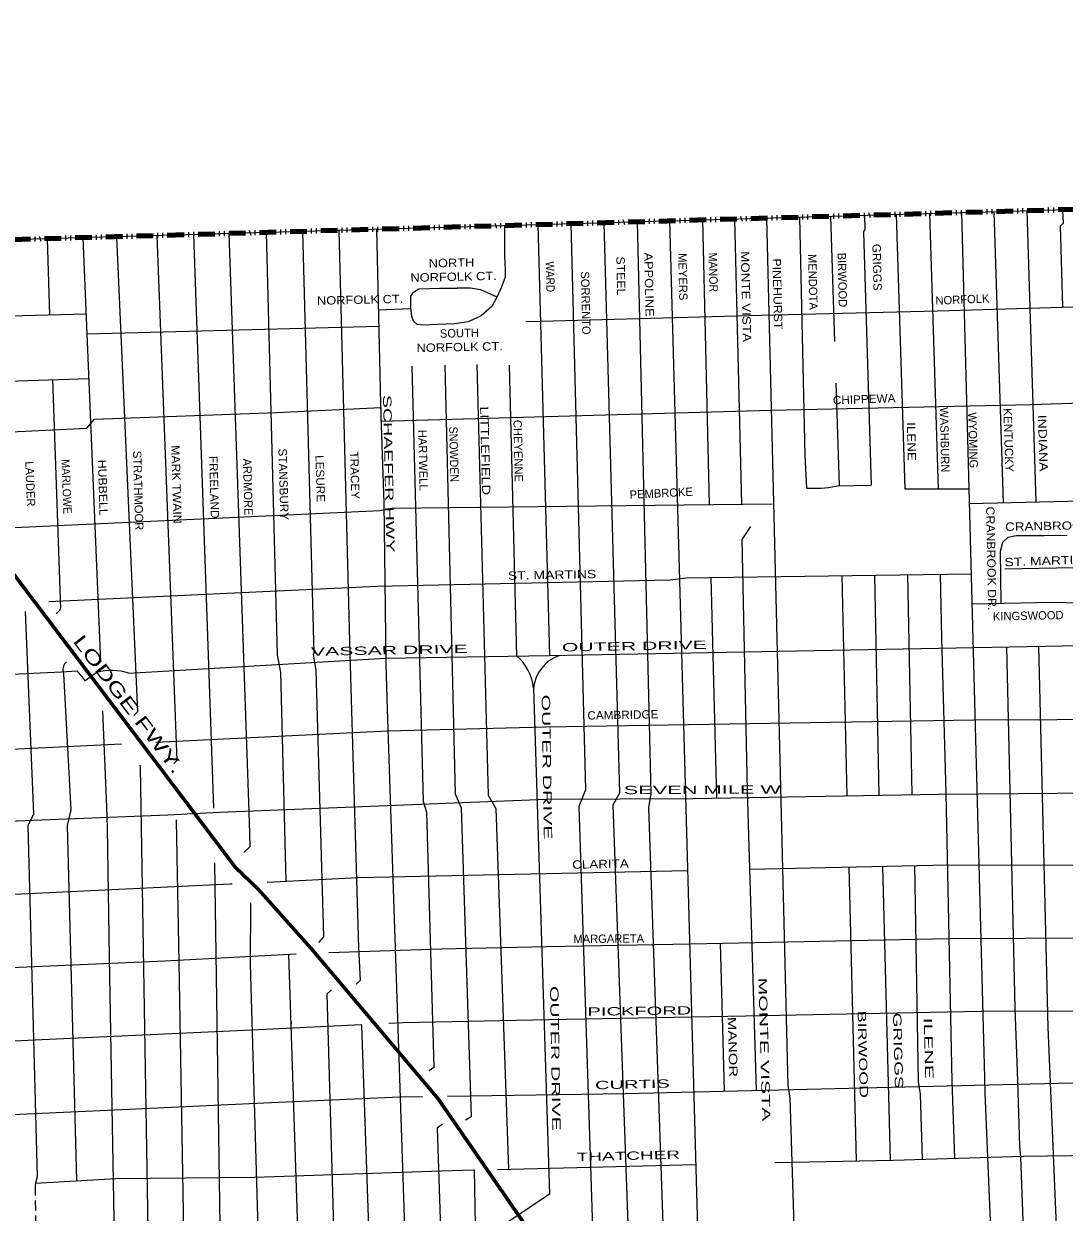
# Model space of a CAD drawing. Extents: x 34705 to 138605, y 34275 to 143551.
# Drawn here: x 60584 to 69930, y 132625 to 143301 of the extents above; entities that cross this region are included whole.
import ezdxf
from ezdxf.enums import TextEntityAlignment as Align

# ---------------------------------------------------------------- set-up
doc = ezdxf.new("R2010")
doc.units = 0
doc.header["$LTSCALE"] = 30
doc.linetypes.add('DASH_DOUBLE_DOT', pattern=[9.2, 5, -1.2, 0.3, -1.2, 0.3, -1.2])
doc.linetypes.add('MEDIUM_DASHED', pattern=[4.5, 3, -1.5])
for name, color, linetype, lineweight in [('1', 7, 'Continuous', 13), ('11', 7, 'Continuous', 13), ('51', 7, 'Continuous', 35), ('59', 7, 'DASH_DOUBLE_DOT', 106)]:
    doc.layers.add(name, color=color, linetype=linetype, lineweight=lineweight)

msp = doc.modelspace()

# ---------------------------------------------------------------- linework, layer by layer
at = {"layer": '1'}
for p, q in [((75780.8, 141796.99), (34922.9, 140631.57)), ((67829.9, 141570.2), (67866.44, 140447.23)), ((68422.1, 141587.09), (68499.45, 139123.37)), ((68719.75, 141595.58), (68796.59, 139123.37)), ((69299.41, 141612.11), (69381.01, 138998.67)), ((69595.74, 141620.57), (69674.85, 139005.55)), ((65202.64, 141495.26), (65306.45, 137625.47)), ((66682.32, 141537.46), (66740.03, 138981.8)), ((66968.64, 141545.63), (67032.3, 138985.16)), ((60795.73, 141369.56), (60815.72, 140686.87)), ((61115.53, 141378.68), (61273.76, 137566.54)), ((62108.83, 141407.01), (62289.02, 136253.43)), ((63769.99, 140730.86), (64061.27, 140743.01)), ((63775.3, 140731.09), (64053.92, 140742.7)), ((59169.39, 140638.51), (61143.85, 140696.51)), ((61151.35, 140515.77), (63773.41, 140585.79)), ((64945.36, 140235.52), (65010.54, 137620.79)), ((59188.11, 140049.59), (61167.99, 140114.8)), ((60843.68, 140104.43), (60913.9, 138048.34)), ((67878.59, 140073.92), (67908.59, 139151.81)), ((68499.45, 139123.37), (68796.18, 139123.37)), ((68796.59, 139123.37), (69073.39, 139123.37)), ((66756.3, 138326.41), (66806.97, 136344.66)), ((67932.67, 138342.52), (67978.14, 136366.05)), ((68225.6, 138346.54), (68265.02, 136371.29)), ((68522.52, 138350.6), (68562.37, 136376.72)), ((61062.26, 137489.13), (61134.92, 137399.56)), ((61240.41, 137472.81), (61134.92, 137399.56)), ((59283.65, 136728.46), (61462.5, 136833.81)), ((67994.83, 135726.36), (68060.94, 133086.13)), ((68297.13, 135732.82), (68367.51, 133092.66)), ((66840.26, 135041.26), (66877.03, 133713.73)), ((62962.12, 134942.93), (63049.9, 132307.68)), ((62984.92, 134336.63), (62985.66, 134313.22)), ((64841.02, 133009.79), (66619.14, 133052.98)), ((69538.12, 133118.98), (69608.88, 131142.6))]:
    msp.add_line(p, q, dxfattribs=at)
at = {"layer": '1', "lineweight": 25}
msp.add_line((69398.11, 138403.72), (70195.7, 138419.82), dxfattribs=at)
at = {"layer": '1'}
for points in [[(68135.27, 141578.91), (68139.56, 141454.62), (68128.57, 141428.99), (68194.72, 139157.43)], [(69007.73, 141603.79), (69213.36, 133836.32), (69216.36, 133697.32), (69320.96, 131186.42), (69315.06, 131084.72), (69664.86, 119741.72), (69733.56, 116534.02), (69862.73, 112612.85), (69926.46, 110045.02), (69944.36, 109925.32), (70046.06, 107393.42), (70046.8, 107365.77)], [(69915.12, 141629.68), (69919.54, 141505.89), (69893.91, 141483.91), (69914.81, 140756.73)], [(64902.36, 141486.69), (64902.36, 141212.02), (64907.16, 141092.32), (64907.16, 141092.32), (64907.16, 141025.32), (64907.16, 141025.32), (64873.66, 140929.62), (64830.56, 140838.62), (64787.46, 140762.02), (64787.46, 140762.02), (64691.76, 140675.92), (64691.76, 140675.92), (64576.96, 140623.22), (64576.96, 140623.22), (64457.26, 140604.12), (64457.26, 140604.12), (64299.36, 140599.32), (64299.36, 140599.32), (64174.96, 140594.52), (64174.96, 140594.52), (64117.56, 140599.32), (64117.56, 140599.32), (64084.06, 140628.02), (64084.06, 140628.02), (64069.66, 140671.12), (64069.66, 140671.12), (64060.16, 140752.52), (64060.16, 140853.02), (64060.16, 140853.02), (64084.06, 140891.32), (64084.06, 140891.32), (64131.86, 140920.02), (64131.86, 140920.02), (64318.56, 140924.82), (64476.46, 140924.82), (64476.46, 140929.62), (64596.06, 140929.62), (64686.96, 140915.22), (64834.62, 140847.2)], [(65499.48, 141503.72), (65630.16, 136420.52), (65570.36, 136270.92), (65706.36, 132112.12), (65712.36, 132106.12), (65563.83, 131997.17)], [(65795.47, 141512.17), (65935.06, 136390.62), (65876.16, 136280.42), (66050.39, 131434.57), (65986.93, 131381.97)], [(66092.89, 141520.65), (66215.86, 136385.72), (66196.76, 136256.42), (66374.79, 131039.01)], [(66384.54, 141528.97), (66709.46, 129789.62), (67063.76, 119831.42), (67307.36, 109342.42), (67367.87, 107615.88)], [(67255.85, 141553.82), (67446.36, 133763.22), (67464.36, 133649.52), (67600.83, 129344.42)], [(67552.7, 141562.29), (67600.06, 139422.92), (67614.55, 139129)], [(61418, 141387.31), (61605.26, 137119.32), (61573.1, 137087.07)], [(61778.59, 141397.59), (61959.36, 136683.62), (61932.42, 136656.69)], [(62425.02, 141416.03), (62607.46, 136131.82), (62613.66, 135907.41), (62559.56, 135856.72)], [(62761.41, 141425.62), (62861.56, 137633.32), (62891.46, 137471.82), (62939.49, 135599.3)], [(63087.56, 141434.93), (63189.16, 137643.42), (63184.46, 137638.62), (63208.36, 137490.22), (63277.76, 135099.22), (63234.66, 135051.32), (63235.6, 135047.59)], [(63412.99, 141444.21), (63513.36, 137639.32), (63591.06, 135004.32), (63605.32, 134705.18), (63570.1, 134671.96)], [(63752.96, 141453.91), (63789.81, 139889.2), (63793.47, 139695.12), (63819.1, 138995.71), (63826.42, 138296.3), (63836.26, 137545.02), (63848.16, 137144.32), (64317.56, 123081.12), (64365.46, 121053.22), (64721.35, 107231.4)], [(65095.4, 140629.17), (65118.32, 140626.4), (67206.49, 140681.91), (68792.65, 140721.29), (70526.74, 140771.8), (71940.97, 140805.23), (74272.36, 140880.84), (75461.59, 140911.06)], [(64069.66, 140225.92), (64172.56, 136315.12), (64201.26, 136219.32), (64266.76, 133924.62), (64224.96, 133894.72)], [(64366.36, 140235.52), (64459.66, 136382.12), (64512.36, 136257.62), (64601.66, 133481.92), (64552.26, 133452.02)], [(64653.46, 140240.32), (64756.36, 136372.52), (64823.36, 136252.82), (64937.2, 133012.12)], [(59480.29, 139828.91), (59597.98, 139835.45), (59708.44, 139806.37), (59877.05, 139719.13), (60097.98, 139660.97), (60411.93, 139631.89), (61150.3, 139666.79), (61220.07, 139748.21), (62853.01, 139809.8), (63790.47, 139854.26), (63792.81, 139729.87), (67294.18, 139829.63), (69631.39, 139881.97), (73731.67, 140014.28), (74283.99, 140031.73), (74481.67, 140025.91), (74586.32, 140008.46), (74708.41, 139991.02), (74882.83, 139927.04), (75039.81, 139857.25), (75214.22, 139735.12), (75359.57, 139624.62), (75516.55, 139455.96)], [(67614.55, 139129), (67746.46, 139129), (67813.96, 139134.62), (67892.7, 139151.5), (68194.72, 139157.43)], [(69076.88, 138991.56), (74010.74, 139107.01), (76740.98, 139179.76)], [(50738.64, 138513.12), (57112.52, 138649.02), (58629.96, 138689.73), (63786.92, 138928.18), (63887.95, 138948.95), (67307.74, 138988.33)], [(67111.96, 138786.32), (67035.36, 138666.62), (67082.75, 136410.01), (67161.94, 133720.53)], [(69363.46, 138094.87), (69358.66, 138563.72), (69377.76, 138645.12), (69425.66, 138688.12), (69497.46, 138702.52), (69751.06, 138702.52), (69956.86, 138707.32)], [(60809.79, 138110.33), (63757.85, 138247.72), (66391.57, 138305.88), (66531.11, 138323.33), (69093.64, 138358.42)], [(68814.76, 138354.61), (68826.4, 137784.27), (68866.96, 136388.12), (68920.36, 133806.42), (68944.14, 133109.88)], [(69100.76, 138089.64), (69827.66, 138104.12), (70062.06, 138099.42), (70062.06, 138099.42), (70062.06, 138099.42), (70062.06, 138104.12), (70114.76, 138075.42), (70114.76, 138075.42), (70133.86, 138061.12)], [(60597.69, 138022), (60672.16, 136200.22), (60619.46, 136094.92), (60702.99, 132942.7), (60690.78, 132885.71)], [(61528.99, 137467.59), (63833.43, 137602.17), (65304.36, 137625.43), (74366.84, 137797)], [(69412.06, 137703.2), (69485.46, 134456.92), (69509.36, 133804.92), (69527.26, 133218.72), (69537.99, 133122.22)], [(69698.84, 137708.63), (69784.46, 134283.52), (69914.64, 131149.2)], [(53493.37, 137247.58), (55711.36, 137334.64), (56560.19, 137346.27), (58566.01, 137375.35), (58653.22, 137392.8), (59132.32, 137411.52), (59231.7, 137404.43), (59333.45, 137404.43), (60923.56, 137480.03), (61062.26, 137489.13)], [(60937.98, 137480.65), (60939.9, 137460.12), (61007.06, 136238.52), (60973.56, 136099.62), (61056.43, 132907.04)], [(65163.88, 137331.21), (65305.76, 132788.02), (64749.46, 132412.01), (64626.83, 132338.41), (62738.28, 132301.61), (61417.93, 132272.99), (59451.71, 132146.22), (58797.67, 132105.33), (50401.39, 131888.61), (50311.46, 131843.63), (50205.17, 131778.2), (50123.42, 131716.87), (50074.37, 131655.53), (50021.66, 131579.38)], [(61291.94, 137128.76), (61327.86, 136263.42), (61333.76, 136078.02), (61351.76, 134911.62), (61399.56, 132225.72), (61423.46, 131027.92), (61417.46, 130908.22), (61411.56, 130776.62), (61507.16, 128312.12), (61742.3, 120367.83), (61692.89, 120365.79), (61799.91, 117890.5)], [(61769.79, 136848.66), (63852.33, 136949.35), (65272.38, 136984.24), (69116.85, 137046.76), (70609, 137052.64)], [(61626.71, 136641.53), (61629.16, 136621.42), (61723.96, 131021.92), (62035.42, 120655.65)], [(35050.01, 135441.89), (38867.68, 135617.88), (40146.22, 135653.27), (40348.36, 135643.16), (42072.86, 135638.1), (42926.9, 135633.05), (44579.39, 135678.54), (51671.96, 135890.86), (53501.32, 135931.3), (56282, 136022.29), (57388.72, 136042.52), (58020.4, 136042.52), (61877.48, 136194.17), (62342.4, 136219.45), (65279.74, 136335.71), (66593.65, 136340.77), (68808.33, 136381.21), (71284.55, 136401.43), (76864.35, 136528)], [(61954.13, 136150.33), (61954.56, 136142.72), (61978.46, 134869.42), (62042.36, 131075.72), (62048.36, 130914.22), (62115.03, 128295.85)], [(67103.44, 135707.3), (68888.66, 135745.47), (70209.87, 135741.11), (71628.47, 135741.11), (72372.66, 135770.19), (74420.96, 135818.2), (74424.57, 135710.79), (76894.17, 135752.64)], [(62297.05, 135763.46), (62365.26, 131075.72), (62344.36, 130944.12), (62416.06, 128330.12), (62656.76, 120429.62), (62644.86, 120256.12), (62691.03, 118537.73)], [(68586.48, 135739.01), (68618.36, 133798.92), (68636.36, 133685.32), (68655.36, 133101.25)], [(62769.67, 135590.68), (63584.89, 135632.07), (66546, 135695.38)], [(53550.94, 135101.37), (53582.01, 135101.37), (53709.91, 135130.45), (53820.38, 135206.05), (53913.4, 135264.21), (54064.57, 135293.29), (56659.03, 135361.62), (58269.5, 135373.26), (58933.73, 135416.88), (59334.89, 135434.33), (59747.68, 135445.96), (62439.54, 135573.91), (62456.11, 135574.75)], [(62618.72, 135406.94), (62619.36, 135402.12), (62618.26, 134857.52), (62709.06, 131753.22), (62734.61, 130998.04), (62608.02, 130996.29), (62607.46, 130842.42), (62772.87, 125681.74), (62971.18, 118628.07)], [(63322.97, 134958.43), (64334.89, 134992.33), (65284.01, 135012.67), (66574.71, 135035.94), (68894.47, 135082.46), (71634.29, 135095.55), (73169.17, 135136.26), (76915.2, 135205.8)], [(53573.66, 134618.55), (54656.13, 134649.19), (55260.78, 134672.45), (58438.1, 134727.7), (59256.06, 134755.82), (59712.8, 134788.77), (61852.33, 134881.83), (63031.64, 134946.77)], [(63344.46, 134618.32), (63306.6, 134583.73), (63368.36, 132381.22), (63370.6, 132313.93)], [(63863.46, 134322.99), (63991.87, 134329.32), (65301.45, 134355.48), (67068.89, 134390.38), (69185.17, 134431.09), (70663.36, 134432.55), (74436.61, 134502.34), (74535.45, 134583.76), (76937.78, 134618.78)], [(53584.37, 134080.29), (53680.84, 134063.25), (53785.5, 134016.72), (53866.89, 133981.83), (53954.1, 133970.2), (56078.13, 134013.12), (57866.77, 134063.76), (58839.26, 134082.14), (59009.31, 134096.69), (61393.03, 134207.19), (62695.36, 134265.35), (63615.75, 134310.76)], [(63615.33, 134309.7), (63616.57, 134300.08), (63687.74, 132320.11)], [(64391.29, 133667.27), (65987.5, 133692.48), (69882.84, 133785.53), (71702.6, 133824.8), (74504.92, 133842.25), (76965.74, 133891.48)], [(48198.29, 133162.97), (49942.48, 133199.59), (53326.19, 133292.64), (58792.75, 133413.32), (59827.63, 133471.48), (61398.85, 133544.18), (62741.87, 133608.16), (63962.8, 133660.5), (64165.31, 133663.7)], [(64344.46, 133416.12), (64296.66, 133380.22), (64375.83, 131013.76)], [(67330.52, 133070.11), (67336.33, 133070.2), (68394.47, 133093.46), (69563.08, 133128.36), (72365.39, 133167.61), (74499.11, 133185.06), (76991.23, 133228.89)], [(60690.78, 132885.71), (61410.47, 132927.7), (62660.47, 132939.34), (64334.89, 132997.49), (64628.67, 133004.63)], [(64630.2, 133007.5), (64641.96, 132345.42), (64691.36, 131063.82), (64643.46, 130962.12), (64656.1, 130351.06)]]:
    msp.add_lwpolyline(points, dxfattribs=at)
at = {"layer": '1', "linetype": 'MEDIUM_DASHED'}
msp.add_lwpolyline([(60690.78, 132885.71), (60686.12, 132863.92), (60691.07, 132313.04)], dxfattribs=at)
at = {"layer": '1'}
for centre, radius, start, end in [((60819.34, 138089.63), 103.18, 302.03448, 336.40724), ((61023.92, 137501.93), 88.54, 130.10803, 193.91147), ((61375.76, 136975.45), 515.44, 72.70484, 105.22386)]:
    msp.add_arc(centre, radius, start, end, dxfattribs=at)
at = {"layer": '11'}
for centre, radius, start, end in [((64732.58, 137291.01), 433.12, 5.32622, 49.98888), ((65509.72, 137298.11), 347.46, 109.24211, 174.53282)]:
    msp.add_arc(centre, radius, start, end, dxfattribs=at)
at = {"layer": '51', "lineweight": 60}
msp.add_lwpolyline([(57328.6, 141592.26), (57571.5, 141277.59), (58004.21, 140952.96), (58644, 140312.96), (59287.28, 139714.93), (59360.7, 139617), (60101.88, 138823.12), (60211.13, 138727.83), (62487.11, 135721.94), (62689.88, 135526.09), (63165.36, 134994.51), (64305.09, 133644.57), (67189.39, 129467.1), (67720.8, 128865.58), (68108.86, 128381.22), (68864.02, 127255.1), (69010.86, 127136.19), (69262.58, 126891.39), (69647.16, 126779.47), (69954.82, 126695.54)], dxfattribs=at)
at = {"layer": '59'}
msp.add_lwpolyline([(131989.06, 109708.72), (126856.28, 120352.83), (127983.73, 120601.28), (129321.71, 120998.46), (130612.42, 121494.12), (133722.19, 123216.65), (134563.84, 124776.42), (136438.38, 130047.1), (136736.54, 131235.05), (136773.12, 131974.15), (125584.57, 138103.26), (128512.62, 143301.1), (34921.35, 140631.52)], dxfattribs=at)

# ---------------------------------------------------------------- texts
at = {"layer": '11'}
for s, height, rotation, width, p in [('GRIGGS', 75, 271.334, 1.05, (68211.98, 141112.8)), ('NORTH ', 75, 1.276, 1.15, (64443.03, 141116.15)), ('WARD', 75, 271.273, 0.9, (65275.92, 141027.53)), ('STEEL', 75, 271.276, 1.1, (65910.53, 141035.1)), ('APPOLINE', 75, 271.274, 1.15, (66163.78, 140957.16)), ('MANOR', 75, 271.334, 0.95, (66739.76, 141066.77)), ('MONTE VISTA', 75, 271.336, 1.2, (67034.67, 140849.73)), ('PINEHURST', 75, 271.336, 1.1, (67317.33, 140873.34)), ('NORFOLK CT.', 75, 1.276, 1.15, (64445.81, 140991.18)), ('NORFOLK CT.', 75, 1.272, 1.15, (63606.24, 140784.8)), ('NORFOLK CT.', 75, 1.272, 1.15, (64500.72, 140359.6)), ('CHIPPEWA', 75, 2.043, 1.05, (68134.17, 139891.62)), ('SCHAEFER HWY', 75, 271.274, 1.75, (63826.04, 139258.93)), ('LITTLEFIELD', 75, 271.274, 1.3, (64692.07, 139464.83)), ('KENTUCKY', 75, 271.817, 1.05, (69392.72, 139560.02)), ('INDIANA', 75, 271.819, 1.25, (69702.01, 139533)), ('SNOWDEN', 75, 271.274, 0.95, (64411.11, 139432.61)), ('ILENE', 75, 271.336, 1.2, (68520.74, 139547.27)), ('MARK TWAIN', 75, 271.639, 1.1, (61918.7, 139162.11)), ('STANSBURY', 75, 271.642, 1.05, (62880.49, 139162.95)), ('TRACEY', 75, 271.643, 1.05, (63520.46, 139244.37)), ('MARLOWE', 75, 272.294, 0.95, (60931.35, 139141.84)), ('HUBBELL', 75, 271.641, 1.1, (61257.54, 139132.3)), ('FREELAND', 75, 271.64, 1.05, (62257.01, 139136.84)), ('LESURE', 75, 271.642, 1.05, (63210.07, 139214.13)), ('ST. MARTINS', 75, 1.924, 1.25, (69790.81, 138440.03)), ('ST. MARTINS', 75, 1.076, 1.25, (65330.15, 138313.35)), ('LODGE FWY.', 120, 307.283, 1.5, (61477.7, 137151.72)), ('OUTER DRIVE', 75, 1.076, 1.9, (66069.67, 137673.78)), ('VASSAR DRIVE', 75, 1.074, 1.9, (63869.08, 137635.99)), ('OUTER DRIVE', 75, 270.907, 1.9, (65246.05, 136623.1)), ('CAMBRIDGE', 75, 1.075, 1.05, (65966.6, 137055.56)), ('SEVEN MILE W', 75, 0.221, 1.95, (66679.65, 136382.93)), ('CLARITA', 75, 1.237, 1.2, (65765.09, 135715.27)), ('OUTER DRIVE', 75, 270.907, 1.9, (65321.79, 134006.09)), ('MONTE VISTA', 75, 271.554, 1.9, (67200.21, 134086.27)), ('PICKFORD', 75, 0.733, 1.8, (66114.35, 134395.53)), ('BIRWOOD', 75, 271.552, 1.6, (68084.31, 134041.64)), ('MANOR', 75, 271.553, 1.45, (66914.85, 134108.4)), ('GRIGGS', 75, 271.552, 1.7, (68400.68, 134075.24)), ('ILENE', 75, 271.554, 1.9, (68674.8, 134096.11)), ('CURTIS', 75, 1.41, 1.8, (66052.23, 133736.42)), ('THATCHER', 75, 1.323, 1.7, (66015.7, 133094.51))]:
    msp.add_text(s, height=height, rotation=rotation, dxfattribs=dict(at, width=width)).set_placement(p, align=Align.CENTER)
for s, rotation, p in [('MEYERS', 271.272, (66467.63, 141027.92)), ('MENDOTA', 271.334, (67635.03, 140981.37)), ('BIRWOOD', 271.336, (67899.87, 140999.11)), ('SORRENTO', 271.273, (65594.28, 140792)), ('NORFOLK', 2.489, (69017.37, 140786.71)), ('SOUTH', 1.272, (64497.95, 140484.57)), ('WASHBURN', 271.336, (68819.32, 139563.04)), ('WYOMING', 271.747, (69073.72, 139558.49)), ('CHEYENNE', 271.273, (64988.59, 139463.34)), ('HARTWELL', 271.273, (64133.67, 139379.57)), ('STRATHMOOR', 271.64, (61574.89, 139106.57)), ('LAUDER', 272.292, (60605.14, 139166.51)), ('ARDMORE', 271.639, (62559.8, 139138.77)), ('PEMBROKE', 2.887, (66312.38, 139047.18)), ('KINGSWOOD', 1.142, (69607.58, 137946.44)), ('MARGARETA', 0.318, (65838.81, 135044.57))]:
    msp.add_text(s, height=75, rotation=rotation, dxfattribs=at).set_placement(p, align=Align.CENTER)
for s, rotation, width, p in [('CRANBROOK DR.', 271.142, 1.1, (69228.52, 138963.03)), ('CRANBROOK DR. ', 1.142, 1.2, (69400.22, 138744.83))]:
    msp.add_text(s, height=75, rotation=rotation, dxfattribs=dict(at, width=width)).set_placement(p)

doc.saveas('drawing.dxf')
